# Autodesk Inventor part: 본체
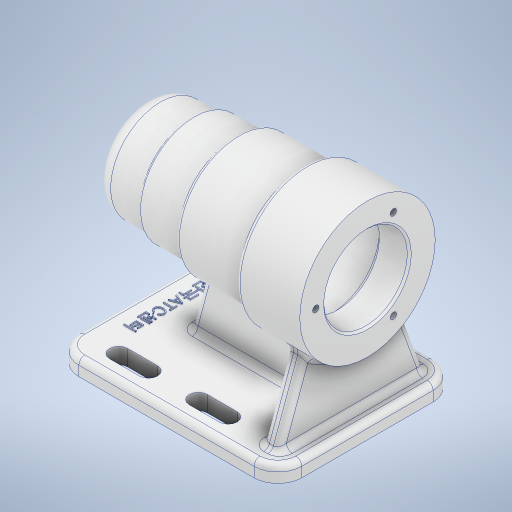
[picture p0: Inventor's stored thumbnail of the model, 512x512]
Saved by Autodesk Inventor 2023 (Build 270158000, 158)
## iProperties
Created: 2022-07
Part Number: 본체
Material: 알루미늄 6061
Document SubType Name: Modeling
Designer: owner
Density: 2.7 g/cm^3
Appearance: 알루미늄 - 평지
Mass: 692.838 g
Surface Area: 701.749 cm^2
Volume: 256.607 cm^3
Author: owner
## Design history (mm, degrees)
sketch "스케치1"
  geometry: L1 (56, -45)-(-56, -45); L2 (-56, -45)-(-56, 45); L3 (-56, 45)-(56, 45); L4 (56, 45)-(56, -45); L5 (56, -45)-(-56, 45); L6 (-56, -45)-(56, 45); 1 further point
  constraints: 12 end point, 2 midpoint, 2 parallel, 1 horizontal, 1 perpendicular
  dimensions: "d0" = 112 distance of L1.start L1.end; "d1" = 90 distance of L1.end L2.end
extrude "돌출1" new body sketch "스케치1" distance "d2" = 8; taper "d3" = 0 deg
sketch "스케치2"
  geometry: L1 (-56, 70)-(56, 70); L2 (-56, 0)-(56, 0) reference; L3 (56, 0)-(56, 8) reference; L4 (-56, 70)-(-56, 87); L5 (-48, 95)-(-33, 95); L6 (-32, 96)-(-32, 96); L7 (-31, 97)-(-11.5, 97); L8 (-10, 98.5)-(-10, 98.5); L9 (-8.5, 100)-(22, 100); L10 (24, 102)-(24, 102); L11 (26, 104)-(56, 104); L12 (56, 104)-(56, 91); L13 (56, 91)-(41, 91); L14 (41, 91)-(41, 91); L15 (38, 94)-(-10, 94); L16 (-13, 91)-(-13, 91); L17 (-13, 91)-(-24.7, 91); L18 (-25, 90.7)-(-25, 87.5); L19 (-25, 87.5)-(-42.7, 87.5); L20 (-43, 87.2)-(-43, 86); L21 (-43, 86)-(-46.7, 86); L22 (-47, 85.7)-(-47, 80.5); L23 (-47, 80.5)-(-47, 80.5); L24 (-50, 77.5)-(-50, 70); A1 r 0.3 centre (-46.7, 85.7) between (-46.7, 86) and (-47, 85.7); A2 r 0.3 centre (-42.7, 87.2) between (-42.7, 87.5) and (-43, 87.2); A3 r 0.3 centre (-24.7, 90.7) between (-24.7, 91) and (-25, 90.7); A4 r 3 centre (-47, 77.5) between (-47, 80.5) and (-50, 77.5); A5 r 3 centre (-10, 91) between (-10, 94) and (-13, 91); A6 r 3 centre (38, 91) between (41, 91) and (38, 94); A7 r 8 centre (-48, 87) between (-48, 95) and (-56, 87); A8 r 1 centre (-31, 96) between (-31, 97) and (-32, 96); A9 r 1 centre (-33, 96) between (-33, 95) and (-32, 96); A10 r 1.5 centre (-8.5, 98.5) between (-8.5, 100) and (-10, 98.5); A11 r 1.5 centre (-11.5, 98.5) between (-11.5, 97) and (-10, 98.5); A12 r 2 centre (26, 102) between (26, 104) and (24, 102); A13 r 2 centre (22, 102) between (22, 100) and (24, 102); 12 further points
  constraints: 44 end point, 26 point on circle, 26 tangent, 20 perpendicular, 13 centre point, 10 point on line, 7 equal radius, 1 horizontal, 1 midpoint, 1 vertical
  dimensions: "d4" = 70 distance from line of point (0, 0) L1; "d5" = 112 distance of L1.start L1.end; "d6" = 21 diameter of L23 L1; "d7" = 50 diameter of L5 L1; "d8" = 32 diameter of L21 L1; "d9" = 35 diameter of L19 L1; "d10" = 42 diameter of L17 L1; "d11" = 48 diameter of L15 L1; "d12" = 42 diameter of L13 L1; "d13" = 54 diameter of L7 L1; "d14" = 60 diameter of L9 L1; "d15" = 68 diameter of L11 L1; "d16" = 24 distance between parallel lines of L6 L4; "d17" = 46 distance between parallel lines of L8 L4; "d18" = 80 distance between parallel lines of L4 L10; "d19" = 112 distance between parallel lines of L4 L12; "d20" = 15 distance between parallel lines of L12 L14; "d21" = 54 distance between parallel lines of L14 L16; "d22" = 12 distance of L16.end point (-25, 91); "d23" = 18 distance of L18.end point (-43, 87.5); "d24" = 4 distance of L20.end point (-47, 86); "d25" = 3 distance of L22.end point (-50, 80.5); "d26" = 0.3 radius of A1; "d27" = 3 radius of A4; "d28" = 8 radius of A7; "d29" = 1 radius of A8; "d30" = 1.5 radius of A10; "d31" = 2 radius of A12
revolve "회전1" sketch "스케치2" stored, may be unused: angle "d32" = 90 deg
chamfer "모따기1" distance "d33" = 1; stored, may be unused: second distance "d34" = 2, angle "d35" = 45 deg
sketch "스케치3"
  geometry: L1 (-36, 33)-(-21, 33); L2 (-36, 28.5)-(-21, 28.5); L3 (-21, 37.5)-(-36, 37.5); L4 (-56, 45)-(-56, -45) reference; L5 (4, 33)-(19, 33); L6 (4, 28.5)-(19, 28.5); L7 (19, 37.5)-(4, 37.5); L8 (-56, 0)-(0, 0); L9 (4, -28.5)-(19, -28.5); L10 (19, -37.5)-(4, -37.5); L11 (-36, -28.5)-(-21, -28.5); L12 (-21, -37.5)-(-36, -37.5); A1 r 4.5 centre (-36, 33) between (-36, 37.5) and (-36, 28.5); A2 r 4.5 centre (-21, 33) between (-21, 28.5) and (-21, 37.5); A3 r 4.5 centre (4, 33) between (4, 37.5) and (4, 28.5); A4 r 4.5 centre (19, 33) between (19, 28.5) and (19, 37.5); A5 r 4.5 centre (19, -33) between (19, -37.5) and (19, -28.5); A6 r 4.5 centre (4, -33) between (4, -28.5) and (4, -37.5); A7 r 4.5 centre (-21, -33) between (-21, -37.5) and (-21, -28.5); A8 r 4.5 centre (-36, -33) between (-36, -28.5) and (-36, -37.5); 2 further points
  constraints: 26 end point, 16 point on circle, 12 symmetric about line, 8 centre point, 8 tangent, 3 midpoint, 2 horizontal, 2 parallel, 2 point on line, 4 other
  dimensions: "d36" = 7.5 distance of point (-28.5, 33) L1.end; "d37" = 9 diameter of A2; "d38" = 20 distance from line of L4 L1.start; "d39" = 33 vertical distance of L8.end point (-28.5, 33); "d40" = 7.5 distance of point (11.5, 33) L5.end; "d41" = 9 diameter of A4; "d42" = 25 distance of L5.start L1.end
extrude "돌출2" cut sketch "스케치3" distance "d43" = 8; taper "d44" = 0 deg
node "작업 평면1"
sketch "스케치5"
  geometry: L1 (45.342, 23.409)-(8, 37); L2 (8, 37)-(8, -37); L3 (8, -37)-(45.342, -23.409); L4 (8, -45)-(8, 45) reference; A1 r 34 centre (70, 0) between (45.342, 23.409) and (45.342, -23.409) reference; 1 further point
  constraints: 6 end point, 2 point on circle, 1 collinear, 1 equal length, 1 vertical
  dimensions: "d46" = 74 distance of L1.end L2.end; "d47" = 110 deg angle of L4 L1; "d48" = 110 deg angle of L4 L3
extrude "돌출3" join sketch "스케치5" distance "d49" = 8; taper "d50" = 0 deg
sketch "스케치6"
  geometry: L1 (-19.622, 43)-(-29, 8); L2 (56, 8)-(-56, 8) reference; L3 (48, 8)-(48, 45.342) reference; L4 (-31, 43)-(-11.5, 43) reference; 1 further point
  constraints: 2 end point, 2 point on line
  dimensions: "d51" = 105 deg angle of L2 L1; "d52" = 77 distance from line of L3 L1.end
feature "리브1" sketch "스케치6" dims "d53" = 1, "d54" = 8, "d55" = 0, "d56" = 0, "d57" = 1, "d58" = 1
fillet "모깎기1" dims "d59" = 12
fillet "모깎기2" dims "d60" = 3
fillet "모깎기3" dims "d61" = 3
fillet "모깎기4" dims "d62" = 3
fillet "모깎기5" dims "d63" = 3
sketch "스케치7" dims "d71" = 52
  geometry: C1 r 10.5 at (0, 0) reference; 3 further points
  constraints: 2 horizontal alignment, 1 coincident, 2 other
hole "구멍1" sketch "스케치7" at (-26, 0) diameter "d64" = 3.242; stored, may be unused: countersink angle "d68" = 90 deg, drill point angle "d70" = 118 deg; dims "d65" = 8, "d66" = 4, "d67" = 2, "d69" = 11
sketch "스케치8"
  geometry: L1 (-56, 33)-(-56, -33) reference; L2 (44, 45)-(-44, 45) reference; 2 further points
  constraints: 1 horizontal alignment, 1 other
  dimensions: "d75" = 12 distance from line of L1 point (-44, 0)
feature "엠보싱1" sketch "스케치8" dims "d0" = 112, "d1" = 90, "d77" = 0.5, "d78" = 0
node "솔리드1"
pattern_circular "원형 패턴1" dims angle "d73" = 360 deg
feature "A9D066F2-1C7D-4E18-AEED-F7BC21143FA4" dims "d64" = 3.242, "d65" = 8, "d66" = 4, "d67" = 2, "d68" = 90 deg, "d69" = 11, "d70" = 118 deg
other parameters: "d45" = 48
